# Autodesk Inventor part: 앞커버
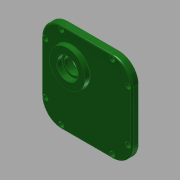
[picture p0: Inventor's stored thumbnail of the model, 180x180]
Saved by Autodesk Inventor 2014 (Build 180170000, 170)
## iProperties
Created: 2016-12
Part Number: 앞커버
Material: 일반
Document SubType Name: Modeling
Designer: mduedu
Density: 1 g/cm^3
Appearance: 매끄러움 - 짙은 산림 녹색
Mass: 191.493 g
Surface Area: 476.271 cm^2
Volume: 191.493 cm^3
Author: mduedu
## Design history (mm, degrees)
sketch "스케치1"
  geometry: L1 (-46, 42)-(-46, -36); L2 (-16, 72)-(62, 72); L3 (92, 42)-(92, -36); L4 (62, -66)-(-16, -66); A1 r 30 centre (-16, -36) between (-46, -36) and (-16, -66); A2 r 30 centre (62, 42) between (92, 42) and (62, 72); A3 r 30 centre (62, -36) between (62, -66) and (92, -36); A4 r 30 centre (-16, 42) between (-16, 72) and (-46, 42); 1 further point
  constraints: 8 end point, 8 point on circle, 8 tangent, 4 centre point, 3 equal radius, 2 perpendicular, 1 horizontal
  dimensions: "d89" = 30 radius of A2; "d90" = 92 distance from line of L3 point (0, 0); "d91" = 138 distance between parallel lines of L4 L2; "d92" = 72 distance from line of point (0, 0) L2; "d114" = 46 distance from line of point (0, 0) L1
extrude "돌출1" new body sketch "스케치1" distance "d3" = 10; taper "d4" = 0 deg
sketch "스케치2"
  geometry: C1 r 21 at (0, 26); 1 further point
  constraints: 1 centre point, 1 vertical alignment
  dimensions: "d5" = 42 diameter of C1; "d7" = 26 distance of C1.centre point (0, 0)
extrude "돌출2" join sketch "스케치2" distance "d8" = 7; taper "d9" = 0 deg
sketch "스케치3"
  geometry: C1 r 15 at (0, -28.87); C2 r 21 at (0, 26) reference; C3 r 15 at (-54.87, 26); 1 further point
  constraints: 2 centre point, 1 horizontal alignment, 1 vertical alignment
  dimensions: "d10" = 30 diameter of C1; "d71" = 54.87 distance of C1.centre C2.centre; "d94" = 30 diameter of C3; "d95" = 54.87 distance of C2.centre C3.centre
extrude "돌출3" join sketch "스케치3" distance "d12" = 7; taper "d13" = 0 deg; dims "d50" = 90 deg
sketch "스케치4"
  geometry: C1 r 21 at (0, 26) reference; C2 r 28 at (0, 26); 1 further point
  constraints: 1 centre point, 1 coincident
  dimensions: "d14" = 56 diameter of C2
extrude "돌출4" join sketch "스케치4" distance "d15" = 7; taper "d16" = -5 deg
hole "구멍1" diameter "d19" = 35; stored, may be unused: countersink angle "d23" = 90 deg, drill point angle "d25" = 0 deg; dims "d17" = 10, "d18" = 10, "d20" = 6, "d21" = 4, "d22" = 2, "d24" = 10
hole "구멍2" diameter "d28" = 22; stored, may be unused: countersink angle "d32" = 90 deg, drill point angle "d34" = 0 deg; dims "d26" = 10, "d27" = 10, "d29" = 6, "d30" = 4, "d31" = 2, "d33" = 7
hole "구멍8" diameter "d98" = 22; stored, may be unused: countersink angle "d102" = 90 deg, drill point angle "d104" = 0 deg; dims "d96" = 10, "d97" = 10, "d99" = 6, "d100" = 4, "d101" = 2, "d103" = 7
hole "구멍3" diameter "d37" = 19; stored, may be unused: countersink angle "d41" = 90 deg, drill point angle "d43" = 0 deg; dims "d35" = 10, "d36" = 10, "d38" = 6, "d39" = 4, "d40" = 2, "d42" = 1
hole "구멍9" diameter "d107" = 19; stored, may be unused: countersink angle "d111" = 90 deg, drill point angle "d113" = 0 deg; dims "d105" = 10, "d106" = 10, "d108" = 6, "d109" = 4, "d110" = 2, "d112" = 1
hole "구멍4" diameter "d46" = 32; stored, may be unused: countersink angle "d50" = 90 deg, drill point angle "d52" = 0 deg; dims "d44" = 10, "d45" = 10, "d47" = 6, "d48" = 4, "d49" = 2, "d51" = 8
hole "구멍5" diameter "d55" = 25; stored, may be unused: countersink angle "d59" = 90 deg, drill point angle "d61" = 0 deg; dims "d53" = 10, "d54" = 10, "d56" = 6, "d57" = 4, "d58" = 2, "d60" = 8
fillet "모깎기1" dims "d62" = 0.3
fillet "모깎기2" dims "d63" = 2
chamfer "모따기1" distance "d64" = 1; stored, may be unused: second distance "d65" = 2, angle "d66" = 45 deg
fillet "모깎기4" dims "d68" = 2
fillet "모깎기5" dims "d69" = 0.3
fillet "모깎기6" dims "d70" = 2
sketch "스케치5"
  geometry: L1 (62, 72)-(-16, 72) reference; L2 (92, -36)-(92, 42) reference; L3 (-16, -66)-(62, -66) reference; L4 (-46, 42)-(-46, -36) reference; L5 (-40, 42)-(-40, -36); L6 (-16, -60)-(62, -60); L7 (86, -36)-(86, 42); L8 (62, 66)-(-16, 66); A1 r 30 centre (62, 42) between (92, 42) and (62, 72) reference; A2 r 30 centre (62, -36) between (62, -66) and (92, -36) reference; A3 r 30 centre (-16, -36) between (-46, -36) and (-16, -66) reference; A4 r 30 centre (-16, 42) between (-16, 72) and (-46, 42) reference; A5 r 24 centre (-16, -36) between (-40, -36) and (-16, -60); A6 r 24 centre (62, -36) between (62, -60) and (86, -36); A7 r 24 centre (62, 42) between (86, 42) and (62, 66); A8 r 24 centre (-16, 42) between (-16, 66) and (-40, 42)
  constraints: 8 end point, 8 point on circle, 4 centre point, 7 other
  dimensions: "d93" = 6 distance between parallel lines of L5 L4
sketch "스케치7"
  geometry: L1 (62, 66)-(-16, 66) reference; L2 (86, -36)-(86, 42) reference; L3 (-16, -60)-(62, -60) reference; L4 (-40, 42)-(-40, -36) reference; A1 r 24 centre (62, 42) between (86, 42) and (62, 66) reference; A2 r 24 centre (62, -36) between (62, -60) and (86, -36) reference; A3 r 24 centre (-16, -36) between (-40, -36) and (-16, -60) reference; A4 r 24 centre (-16, 42) between (-16, 66) and (-40, 42) reference; 8 further points
  constraints: 8 coincident
hole "구멍7" sketch "스케치7" at (-40, 42), (-40, -36), (-16, -60), (62, -60), (86, -36), (86, 42), (62, 66), (-16, 66) diameter "d80" = 4.5; stored, may be unused: countersink angle "d84" = 90 deg, drill point angle "d86" = 0 deg; dims "d81" = 6, "d82" = 8, "d83" = 4.6, "d85" = 8
node "솔리드1"
